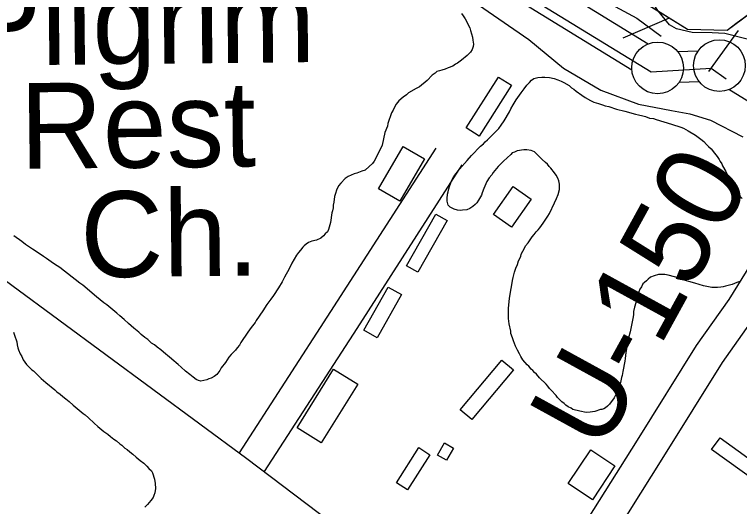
# Model space of a CAD drawing. Extents: x 3823584 to 3861785, y 301729 to 327625.
# Drawn here: x 3839341 to 3840042, y 321976 to 322453 of the extents above; entities that cross this region are included whole.
import ezdxf

# ---------------------------------------------------------------- set-up
doc = ezdxf.new("R2010")
doc.units = 0
for name, color, linetype in [('V-BLDG-OTLN', 7, 'Continuous'), ('V-FLOD-BASE', 7, 'Continuous'), ('V-LEVE-TOET', 7, 'Continuous'), ('V-RIVR-EDGE', 7, 'Continuous'), ('V-RIVR-RANG-IDEN', 7, 'Continuous'), ('V-ROAD-CNTR', 7, 'Continuous'), ('V-RRAP-FSHR', 7, 'Continuous'), ('V-SITE-OTLN-IDEN', 7, 'Continuous'), ('V-SITE-VEGE', 7, 'Continuous'), ('V-SURV-LINE', 7, 'Continuous')]:
    doc.layers.add(name, color=color, linetype=linetype)

msp = doc.modelspace()

# ---------------------------------------------------------------- linework, layer by layer
at = {"layer": 'V-BLDG-OTLN'}
for points in [[(3839821.6, 322383.98), (3839790.29, 322334.71), (3839777.72, 322342.7), (3839809.03, 322391.97)], [(3839737.36, 322312.84), (3839713.57, 322271.92), (3839692.83, 322283.97), (3839716.62, 322324.9)], [(3839840.53, 322273.75), (3839821.45, 322246.66), (3839804.06, 322258.91), (3839823.14, 322285.99)], [(3839759.42, 322253.08), (3839730.89, 322203.14), (3839719.85, 322209.45), (3839748.38, 322259.38)], [(3839715.19, 322181.4), (3839691.42, 322139.78), (3839678.61, 322147.1), (3839702.38, 322188.72)], [(3839823.37, 322108.67), (3839783.09, 322060.69), (3839772.03, 322069.98), (3839812.31, 322117.95)], [(3839672.8, 322094.84), (3839637.42, 322037.94), (3839614.1, 322052.44), (3839649.47, 322109.34)], [(3840023.39, 322042.83), (3840067.84, 322010.8), (3840059.68, 321999.48), (3840015.23, 322031.52)], [(3839765.4, 322032.93), (3839758.6, 322021.14), (3839749.9, 322026.15), (3839756.7, 322037.94)], [(3839742.68, 322026.52), (3839720.9, 321992.51), (3839710.13, 321999.41), (3839731.91, 322033.42)], [(3839921.69, 322015.64), (3839899.9, 321983.01), (3839876.45, 321998.67), (3839898.24, 322031.29)]]:
    msp.add_lwpolyline(points, close=True, dxfattribs=at)
at = {"layer": 'V-FLOD-BASE'}
for points in [[(3838540.65, 323375.59), (3838681.58, 323274.69), (3838841.31, 323153.83), (3838934.47, 323084.95), (3838984.37, 323049.64), (3839079.88, 322986.79), (3839172.37, 322925.72), (3839309, 322835.6), (3839392.4, 322782.86), (3839486.35, 322726.31), (3839628.68, 322636.84), (3839751.95, 322561.62), (3839893.04, 322476.05), (3839942.86, 322448.85), (3839966.45, 322431.64)], [(3839513.67, 322668.2), (3839868.52, 322451.01), (3839956.6, 322397.14), (3840014.74, 322400.56), (3840029.38, 322390.39)]]:
    msp.add_lwpolyline(points, dxfattribs=at)
at = {"layer": 'V-LEVE-TOET'}
for points in [[(3840049.71, 322428.78), (3840028.03, 322433.99), (3840015.7, 322434.78), (3839996.47, 322435.21), (3839981.41, 322438.68), (3839974.47, 322442.53), (3839963.23, 322456.24), (3839959.57, 322461.92), (3839948.36, 322472.64), (3839922.39, 322487.13), (3839751.66, 322594.07), (3839610.87, 322679.65), (3839498.5, 322745.65), (3839372.86, 322817.24), (3839262.27, 322885.96), (3839170.03, 322953.04), (3839027.04, 323048.82), (3838894.93, 323138.38), (3838796.61, 323212.92), (3838670.49, 323304.34), (3838542.35, 323398.37)], [(3839775.14, 322472.06), (3839838.33, 322428.16), (3839871.93, 322400.52), (3839908.18, 322379.21), (3839944.36, 322365.71), (3839976.56, 322359.69), (3839994.02, 322356.23), (3840014.21, 322350.41), (3840045.6, 322334.16)]]:
    msp.add_lwpolyline(points, dxfattribs=at)
at = {"layer": 'V-RIVR-EDGE'}
msp.add_spline([(3836304.38, 325474.18), (3836346.41, 325438.32), (3836389.41, 325406.07), (3836417.64, 325385.43), (3836442.67, 325366.73), (3836470.25, 325340.95), (3836497.82, 325313.88), (3836554.9, 325258.45), (3836598.51, 325215.91), (3836636.36, 325181.1), (3836681.26, 325139.85), (3836737.07, 325093.42), (3836790.94, 325041.22), (3836840.33, 324993.52), (3836889.07, 324947.12), (3836934.61, 324907.14), (3836980.81, 324871.03), (3837015.47, 324849.09), (3837040.49, 324829.1), (3837085.39, 324787.2), (3837143.76, 324734.34), (3837181.61, 324700.82), (3837223.29, 324659.57), (3837272.05, 324619.59), (3837314.38, 324579.63), (3837346.45, 324546.76), (3837364.4, 324527.43), (3837395.83, 324500.35), (3837442.02, 324462.31), (3837492.71, 324422.97), (3837554.31, 324372.67), (3837573.56, 324361.05), (3837583.2, 324359.1), (3837596.69, 324352.64), (3837621.08, 324337.79), (3837648.03, 324319.73), (3837677.54, 324292.01), (3837718.58, 324249.48), (3837753.85, 324214.68), (3837781.43, 324188.89), (3837800.05, 324179.85), (3837819.95, 324170.8), (3837850.72, 324134.08), (3837874.45, 324110.23), (3837909.07, 324073.5), (3837941.78, 324040.64), (3837989.87, 323991.66), (3838022.58, 323960.72), (3838034.12, 323947.83), (3838046.3, 323933.66), (3838066.83, 323916.25), (3838089.91, 323892.41), (3838140.59, 323849.21), (3838186.14, 323811.17), (3838215.65, 323785.38), (3838265.68, 323736.4), (3838297.1, 323707.39), (3838336.87, 323671.94), (3838359.95, 323645.52), (3838385.62, 323627.46), (3838404.24, 323615.84), (3838421.56, 323601.65), (3838441.44, 323582.32), (3838460.05, 323567.49), (3838468.4, 323563.61), (3838484.45, 323555.21), (3838548.59, 323496.55), (3838595.44, 323464.29), (3838649.98, 323422.37), (3838701.3, 323379.82), (3838749.43, 323345.62), (3838798.22, 323317.86), (3838856.62, 323274.64), (3838932.99, 323221.74), (3838989.47, 323184.31), (3839037.6, 323150.12), (3839068.42, 323134.62), (3839093.42, 323104.98), (3839110.73, 323086.94), (3839122.93, 323081.12), (3839143.46, 323065.64), (3839172.34, 323044.36), (3839190.96, 323032.74), (3839215.99, 323015.96), (3839242.32, 323006.26), (3839316.8, 322969.43), (3839341.84, 322955.87), (3839371.38, 322944.22), (3839391.29, 322935.81), (3839417.61, 322920.32), (3839461.26, 322894.5), (3839483.71, 322873.23), (3839520.3, 322851.28), (3839555.6, 322828.69), (3839599.9, 322806.72), (3839718.7, 322751.14), (3839768.14, 322726.59), (3839807.95, 322705.92), (3839836.85, 322696.21), (3839865.1, 322680.71), (3839887.57, 322667.8), (3839924.17, 322652.28), (3839969.76, 322630.31), (3840004.43, 322612.22), (3840037.82, 322597.35), (3840085.35, 322579.88), (3840108.46, 322565.68), (3840121.92, 322548.93), (3840123.18, 322539.92), (3840122.53, 322533.5), (3840118, 322521.29), (3840112.84, 322514.24), (3840095.47, 322509.14), (3840089.68, 322509.15), (3840085.17, 322504.66), (3840084.51, 322498.23), (3840085.78, 322491.8), (3840130.72, 322467.26), (3840169.89, 322448.52), (3840197.51, 322439.45), (3840209.08, 322437.5), (3840231.59, 322441.3), (3840246.39, 322448.98), (3840266.34, 322458.57), (3840273.43, 322466.27), (3840278.59, 322471.4), (3840288.9, 322480.37), (3840295.98, 322484.85), (3840301.77, 322484.84), (3840308.2, 322484.82), (3840320.4, 322479.01), (3840324.87, 322470), (3840326.78, 322461.63), (3840338.32, 322450.03), (3840344.74, 322444.88), (3840366.58, 322437.75), (3840385.84, 322428.06), (3840421.8, 322409.33), (3840466.1, 322385.43), (3840492.41, 322368.65), (3840506.53, 322357.04), (3840533.49, 322340.26), (3840559.18, 322331.2), (3840587.44, 322322.13), (3840611.85, 322311.78), (3840642.02, 322296.28), (3840678.62, 322276.26), (3840712.64, 322255.6), (3840733.18, 322242.05), (3840784.53, 322210.43), (3840835.89, 322183.3), (3840892.39, 322153.59), (3840923.85, 322139.37), (3840950.82, 322127.08), (3840989.33, 322099.99), (3841017.57, 322082.56), (3841061.24, 322062.52), (3841092.69, 322044.45), (3841151.1, 322005.09), (3841210.78, 321964.44), (3841240.29, 321939.29), (3841299.97, 321894.79), (3841335.89, 321862.55), (3841374.37, 321823.89), (3841411.57, 321789.72), (3841444.92, 321758.14), (3841469.94, 321736.22), (3841482.12, 321723.98), (3841496.22, 321704.66), (3841509.05, 321694.34), (3841523.18, 321687.23), (3841573.9, 321660.75), (3841623.97, 321631.69), (3841667.62, 321606.51), (3841696.52, 321593.59), (3841738.26, 321575.48), (3841787.07, 321556.72), (3841815.99, 321552.15), (3841851.33, 321544.99), (3841886.66, 321533.33), (3841930.32, 321511.36), (3841950.22, 321498.46), (3841977.18, 321482.96), (3841998.38, 321476.48), (3842052.99, 321463.49), (3842082.55, 321456.34), (3842109.52, 321444.7), (3842146.12, 321427.26), (3842196.2, 321402.06), (3842241.13, 321374.95), (3842288.63, 321345.26), (3842321.38, 321327.18), (3842366.94, 321295.56), (3842395.19, 321280.07), (3842429.22, 321264.55), (3842452.35, 321258.71), (3842470.97, 321249.66)], degree=3, dxfattribs=at)
at = {"layer": 'V-ROAD-CNTR'}
for points in [[(3835362.23, 325460.93), (3835509.51, 325334.35), (3835871.75, 325022.77), (3836108.4, 324817.6), (3836413.99, 324556.93), (3836839.75, 324193.66), (3837163.69, 323918.79), (3837445.02, 323669.36), (3837836.48, 323328.41), (3838069.57, 323134.88), (3838125.38, 323086.8), (3838255.98, 322989.46), (3838600, 322735.35), (3839019.31, 322425.42), (3839565.54, 322022.91), (3840024.88, 321675.23), (3840474.87, 321349.99), (3840728.36, 321161.31)], [(3839558.36, 322028.2), (3839646.9, 322165.05), (3839748.66, 322323.27)], [(3839582.41, 322010.14), (3839672.11, 322148.79), (3839773.89, 322307.04)], [(3839814.72, 321834.3), (3839839.98, 321872.63), (3839864.64, 321914.99), (3839943.64, 322040.76), (3840000.73, 322132.32), (3840032.17, 322176.76), (3840097.62, 322282.51)], [(3839838.69, 321816.16), (3839865.49, 321856.81), (3839890.31, 321899.46), (3839969.07, 322024.84), (3840025.72, 322115.71), (3840060.61, 322165.01)]]:
    msp.add_lwpolyline(points, dxfattribs=at)
at = {"layer": 'V-RRAP-FSHR'}
for p, q in [((3839974.08, 322448.84), (3839929.17, 322429.68)), ((3840040.93, 322436.88), (3840012.14, 322397.44))]:
    msp.add_line(p, q, dxfattribs=at)
for points in [[(3840073.37, 322469.22), (3840030.26, 322437.09), (3839991.75, 322437.85), (3839543.71, 322716.63)], [(3839974.08, 322448.84), (3839914.65, 322485.83)], [(3840098.52, 322465.57), (3840091.92, 322469.18), (3840081.41, 322471.98), (3840073.37, 322469.22), (3840038.81, 322443.47)], [(3840038.81, 322443.47), (3840030.26, 322437.09), (3839991.75, 322437.85), (3839974.08, 322448.85)]]:
    msp.add_lwpolyline(points, dxfattribs=at)
at = {"layer": 'V-SITE-VEGE'}
for points in [[(3839774.74, 322451.26), (3839776.58, 322448.27), (3839778.1, 322446.18), (3839779.32, 322443.19), (3839781.16, 322439.6), (3839781.78, 322436.9), (3839783.94, 322430.61), (3839784.27, 322427.61), (3839784.91, 322423.71), (3839784.63, 322421.6), (3839783.45, 322418.59), (3839781.97, 322416.17), (3839778.7, 322412.84), (3839773.33, 322408.28), (3839769.45, 322405.54), (3839767.35, 322404.32), (3839764.67, 322402.49), (3839760.17, 322400.95), (3839757.48, 322399.73), (3839754.18, 322398.8), (3839751.79, 322397.88), (3839749.39, 322397.25), (3839747.6, 322395.73), (3839744.91, 322393.91), (3839739.85, 322388.75), (3839732.39, 322382.38), (3839729.4, 322380.85), (3839721.93, 322376.57), (3839719.84, 322374.75), (3839716.85, 322372.62), (3839712.68, 322368.98), (3839710.01, 322365.65), (3839708.52, 322363.53), (3839707.05, 322359.91), (3839705.58, 322357.2), (3839704.4, 322354.48), (3839702.94, 322349.96), (3839702.06, 322346.95), (3839701.48, 322344.54), (3839699.13, 322338.21), (3839696.54, 322326.17), (3839690.93, 322314.7), (3839688.57, 322310.47), (3839687.08, 322308.35), (3839683.81, 322305.32), (3839679.93, 322301.98), (3839676.63, 322301.05), (3839671.84, 322298.9), (3839669.44, 322298.28), (3839663.46, 322295.82), (3839660.47, 322293.69), (3839656.3, 322289.45), (3839654.22, 322286.73), (3839652.16, 322282.5), (3839651.29, 322279.19), (3839650.41, 322276.48), (3839649.56, 322270.76), (3839648.98, 322268.05), (3839649, 322265.35), (3839648.43, 322262.64), (3839647.85, 322260.53), (3839646.43, 322251.2), (3839644.39, 322244.57), (3839643.51, 322242.16), (3839641.42, 322240.34), (3839639.64, 322238.22), (3839636.95, 322236.09), (3839632.76, 322234.25), (3839628.26, 322233.01), (3839625.27, 322231.78), (3839622.88, 322230.25), (3839621.09, 322228.74), (3839619.6, 322227.22), (3839617.52, 322224.5), (3839615.44, 322222.08), (3839613.66, 322219.66), (3839608.92, 322211.8), (3839606.57, 322206.37), (3839601.83, 322198.22), (3839599.77, 322193.69), (3839596.22, 322187.95), (3839591.17, 322180.69), (3839588.8, 322177.07), (3839584.94, 322171.92), (3839581.09, 322165.88), (3839574.56, 322156.51), (3839573.38, 322154.39), (3839569.52, 322149.55), (3839566.56, 322145.02), (3839559.73, 322135.04), (3839558.25, 322132.62), (3839556.17, 322129.9), (3839554.39, 322127.78), (3839550.22, 322123.54), (3839548.14, 322120.81), (3839544.88, 322115.68), (3839540.72, 322110.53), (3839539.24, 322108.11), (3839536.57, 322104.18), (3839533.89, 322102.06), (3839530.89, 322100.53)], [(3839773.22, 322453.35), (3839774.74, 322451.26)], [(3839813.72, 322310.48), (3839808.66, 322305.33), (3839803.91, 322299.58), (3839802.42, 322297.46), (3839800.04, 322294.43), (3839797.67, 322290.81), (3839794.73, 322284.17), (3839793.26, 322279.95), (3839792.69, 322277.84), (3839789.72, 322272.71), (3839787.94, 322270.29), (3839786.46, 322268.77), (3839784.07, 322266.65), (3839781.38, 322264.82), (3839778.39, 322263.59), (3839774.18, 322263.25), (3839772.08, 322262.93), (3839769.38, 322263.21), (3839766.06, 322264.08), (3839762.14, 322266.15), (3839760.32, 322267.94), (3839759.38, 322271.84), (3839759.36, 322274.54), (3839759.62, 322278.74), (3839760.2, 322280.86), (3839760.78, 322283.87), (3839761.66, 322285.98), (3839763.71, 322292.3), (3839765.78, 322295.63), (3839771.12, 322302.89), (3839778.56, 322311.07), (3839782.73, 322315.91), (3839791.66, 322325.01), (3839794.64, 322327.44), (3839796.13, 322329.26), (3839798.21, 322331.38), (3839801.79, 322334.71), (3839809.23, 322342.29), (3839811.61, 322345.32), (3839814.58, 322349.55), (3839819.61, 322358.31), (3839821.08, 322361.33), (3839823.15, 322364.95), (3839826.11, 322369.79), (3839830.86, 322376.74), (3839833.83, 322380.67), (3839836.5, 322384), (3839838.88, 322386.73), (3839840.97, 322388.85), (3839843.35, 322390.67), (3839846.95, 322391.61), (3839850.86, 322391.94), (3839853.86, 322391.97), (3839858.37, 322391.41), (3839862.89, 322390.55), (3839866.5, 322389.38), (3839869.52, 322387.9), (3839872.23, 322386.73), (3839877.37, 322383.77), (3839879.79, 322381.69), (3839881.91, 322380.2), (3839884.03, 322378.42), (3839889.77, 322374.56), (3839892.8, 322372.19)], [(3839892.8, 322372.19), (3839897.93, 322369.23), (3839901.25, 322367.76), (3839903.66, 322367.17), (3839905.77, 322366.29), (3839909.69, 322365.12), (3839912.1, 322364.25), (3839915.71, 322363.38), (3839923.25, 322361.04), (3839931.38, 322359.01), (3839941.62, 322356.1), (3839944.33, 322355.52), (3839948.55, 322354.35), (3839951.25, 322353.78), (3839955.17, 322352.31), (3839959.09, 322351.75), (3839961.5, 322350.86), (3839976.56, 322346.49), (3839985.3, 322343.57), (3839988.02, 322342.39), (3839992.54, 322340.03), (3839999.79, 322335.88), (3840004.94, 322331.73), (3840007.66, 322329.65), (3840010.39, 322326.67), (3840012.21, 322324.88), (3840014.93, 322322.5), (3840017.98, 322318.32), (3840020.71, 322315.04), (3840022.54, 322312.05), (3840023.46, 322310.26), (3840024.98, 322307.86), (3840025.9, 322306.07), (3840028.95, 322300.69), (3840030.48, 322297.4), (3840031.41, 322294.4), (3840032.63, 322292.31), (3840033.86, 322289.32), (3840035.69, 322286.03), (3840037.83, 322282.74), (3840039.05, 322280.65), (3840044.81, 322274.39)], [(3839933.4, 322132.77), (3839932.26, 322125.55), (3839931.99, 322122.54), (3839931.42, 322119.53), (3839931.14, 322117.12), (3839929.43, 322107.19), (3839928.56, 322103.28), (3839927.98, 322101.17), (3839927.4, 322097.86), (3839926.54, 322093.95), (3839925.07, 322090.03), (3839923.6, 322086.71), (3839920.94, 322081.58), (3839916.49, 322075.53), (3839914.4, 322073.4), (3839912.61, 322071.89), (3839910.82, 322070.97), (3839909.02, 322070.35), (3839907.82, 322070.34), (3839902.13, 322068.49), (3839897.63, 322067.55), (3839893.72, 322067.51), (3839887.7, 322068.66), (3839881.08, 322070.4), (3839879.26, 322071.59), (3839876.55, 322072.77), (3839874.13, 322074.55), (3839872.61, 322076.04), (3839870.19, 322077.82), (3839865.95, 322081.98), (3839864.73, 322083.78), (3839859.88, 322089.14), (3839858.36, 322090.63), (3839856.84, 322092.72), (3839855.02, 322094.81), (3839848.65, 322101.06), (3839845.92, 322104.34), (3839843.8, 322106.12), (3839842.28, 322107.91), (3839840.76, 322109.4), (3839838.34, 322112.09), (3839836.82, 322113.58), (3839832.57, 322118.35), (3839830.74, 322121.64), (3839829.21, 322124.03), (3839827.38, 322127.61), (3839825.54, 322131.5), (3839823.39, 322136.59), (3839822.46, 322139.59), (3839820.93, 322143.78), (3839820.9, 322146.19), (3839819.34, 322153.08), (3839818.69, 322158.18), (3839818.6, 322168.4), (3839819.72, 322177.72), (3839820.57, 322183.74), (3839822.01, 322190.97), (3839822.57, 322195.18), (3839823.14, 322197.89), (3839824.6, 322203.31), (3839825.77, 322206.93), (3839827.24, 322210.54), (3839828.41, 322214.16), (3839830.47, 322218.38), (3839831.06, 322220.49), (3839834.01, 322226.53), (3839835.19, 322228.64), (3839837.57, 322231.67), (3839841.72, 322237.42), (3839843.51, 322239.54), (3839845.58, 322242.26), (3839847.37, 322244.08), (3839849.15, 322246.2), (3839852.12, 322250.73), (3839854.79, 322254.36), (3839856.87, 322257.38), (3839858.35, 322259.8), (3839863.06, 322270.36), (3839865.13, 322274.58), (3839866.6, 322278.2), (3839868.06, 322283.02), (3839868.01, 322288.43), (3839867.38, 322291.43), (3839866.45, 322294.13), (3839864.93, 322297.12), (3839863.1, 322299.2), (3839859.76, 322303.68), (3839857.94, 322305.47), (3839856.42, 322307.56), (3839854.6, 322309.34), (3839851.27, 322312.32), (3839845.51, 322317.98), (3839843.69, 322319.46), (3839840.67, 322320.94), (3839836.46, 322321.5), (3839833.46, 322321.47), (3839827.16, 322320.52), (3839824.46, 322319.29), (3839822.36, 322318.67), (3839820.88, 322317.15), (3839813.72, 322310.48)], [(3839530.89, 322100.53), (3839528.8, 322099.91), (3839526.7, 322098.99), (3839521, 322097.74), (3839518.59, 322098.31), (3839516.48, 322099.2), (3839513.46, 322101.57), (3839510.43, 322104.25), (3839506.19, 322107.52), (3839501.95, 322111.39), (3839498.92, 322113.76), (3839497.1, 322115.55), (3839494.68, 322117.33), (3839490.75, 322120.9), (3839488.63, 322122.38), (3839487.12, 322123.87), (3839482.27, 322128.04), (3839478.64, 322130.71), (3839476.22, 322132.79), (3839473.2, 322134.57), (3839469.56, 322138.14), (3839466.84, 322139.92), (3839463.21, 322142.89), (3839461.08, 322144.97), (3839456.24, 322148.84), (3839450.79, 322153.6), (3839446.85, 322157.46), (3839442.61, 322161.03), (3839439.59, 322163.41), (3839429.9, 322171.44), (3839427.18, 322173.52), (3839419.91, 322179.46), (3839406.89, 322190.46), (3839403.87, 322192.54), (3839384.5, 322207.69), (3839379.37, 322210.95), (3839376.04, 322213.32), (3839371.5, 322216.29), (3839368.78, 322218.37), (3839364.55, 322221.33), (3839357.9, 322225.48), (3839354.27, 322228.15), (3839351.25, 322229.93), (3839347.62, 322232.9), (3839340.06, 322238.24)], [(3840042.53, 322194.14), (3840039.53, 322193.21), (3840035.04, 322191.37), (3840028.75, 322189.51), (3840026.35, 322188.89), (3840024.25, 322188.57), (3840020.95, 322188.24), (3840015.54, 322188.19), (3840007.41, 322189.92), (3840003.19, 322191.08), (3839998.97, 322192.55), (3839993.25, 322194), (3839988.73, 322195.46), (3839984.21, 322197.23), (3839973.06, 322200.13), (3839970.05, 322201), (3839963.74, 322200.95), (3839959.54, 322199.71), (3839956.25, 322198.48), (3839953.87, 322196.35), (3839952.38, 322194.84), (3839950.29, 322193.32), (3839948.8, 322191.8), (3839947.32, 322189.08), (3839945.84, 322186.67), (3839944.66, 322184.25), (3839942.62, 322177.02), (3839941.75, 322173.41), (3839940.59, 322169.19), (3839939.73, 322164.98), (3839939.75, 322162.27), (3839939.47, 322159.87), (3839936.29, 322145.42), (3839934.84, 322139.69), (3839933.4, 322132.77)], [(3839339.58, 322145.25), (3839341.12, 322140.16), (3839342.35, 322137.76), (3839342.97, 322135.66), (3839343.29, 322132.96), (3839343.92, 322129.97), (3839344.54, 322127.87), (3839346.07, 322124.27), (3839347.6, 322121.59), (3839349.13, 322118.29), (3839350.65, 322116.2), (3839352.18, 322113.81), (3839357.33, 322108.75), (3839359.14, 322107.57), (3839366.42, 322100.42), (3839368.84, 322098.34), (3839370.96, 322096.25), (3839379.74, 322089.42), (3839381.56, 322087.34), (3839384.88, 322085.26), (3839387.31, 322082.88), (3839390.33, 322080.5), (3839393.66, 322078.13), (3839397.3, 322074.55), (3839406.99, 322066.53), (3839409.1, 322065.04), (3839412.13, 322062.37), (3839417.59, 322057.01), (3839421.22, 322053.73), (3839426.97, 322048.98), (3839430.9, 322046.31), (3839433.63, 322044.23), (3839436.66, 322041.55), (3839439.37, 322040.08), (3839442.41, 322037.1), (3839444.52, 322035.61), (3839447.55, 322032.94), (3839449.67, 322031.46), (3839452.09, 322029.37), (3839455.11, 322027), (3839458.45, 322024.02), (3839462.38, 322021.05), (3839465.71, 322018.38), (3839468.74, 322015.4), (3839470.56, 322013.31), (3839473.29, 322010.93), (3839474.2, 322009.14), (3839476.07, 322002.84), (3839476.7, 321998.64), (3839477.05, 321993.84), (3839476.48, 321989.63), (3839475.6, 321986.91), (3839474.72, 321985.1), (3839472.65, 321982.08), (3839469.37, 321978.45), (3839466.69, 321975.72)]]:
    msp.add_lwpolyline(points, dxfattribs=at)
at = {"layer": 'V-SURV-LINE'}
for points in [[(3839366.34, 322785.06), (3839953.8, 322424.06)], [(3839938.08, 322398.51), (3839350.62, 322759.51)], [(3839982.37, 322416.56), (3840002.26, 322417.31)], [(3840003.4, 322387.33), (3839983.51, 322386.58)], [(3841446.61, 321507.58), (3840031.94, 322379.82)]]:
    msp.add_lwpolyline(points, dxfattribs=at)
for centre in [(3840022.8, 322403.07), (3839962.97, 322400.83)]:
    msp.add_circle(centre, 25, dxfattribs=at)

# ---------------------------------------------------------------- texts
at = {"layer": 'V-RIVR-RANG-IDEN'}
msp.add_text('U-150', height=83, rotation=61.23833, dxfattribs=at).set_placement((3839908.58, 322027.19))
at = {"layer": 'V-SITE-OTLN-IDEN'}
for s, p in [('Pilgrim', (3839292.97, 322402.85)), ('Rest', (3839346.29, 322303.07)), ('Ch.', (3839404.74, 322198.06))]:
    msp.add_text(s, height=83, rotation=0.61622, dxfattribs=at).set_placement(p)

doc.saveas('drawing.dxf')
